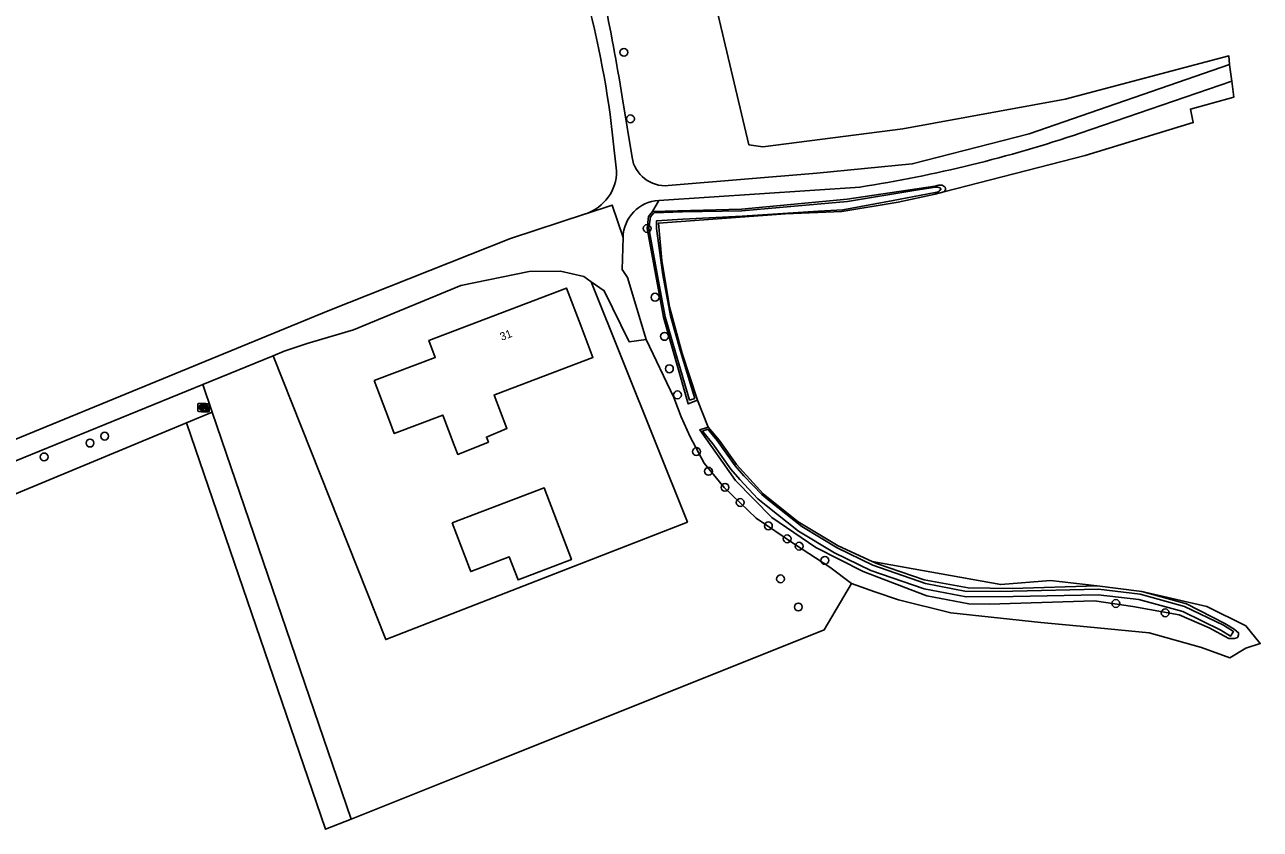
# Model space of a CAD drawing. Extents: x 162515 to 163909, y 388494 to 389773.
# Drawn here: x 162727.4 to 162881.8, y 389491.8 to 389592.3 of the extents above; entities that cross this region are included whole.
import ezdxf

# ---------------------------------------------------------------- set-up
doc = ezdxf.new("R2010")
doc.units = 0
for name, color, linetype in [('IMGEO_Boom', 7, 'Continuous'), ('IMGEO_Grasland_agrarisch', 7, 'Continuous'), ('IMGEO_Grasland_overig', 7, 'Continuous'), ('IMGEO_Groenvoorziening', 7, 'Continuous'), ('IMGEO_Kast', 7, 'Continuous'), ('IMGEO_Loofbos', 7, 'Continuous'), ('IMGEO_Pand', 7, 'Continuous'), ('IMGEO_Pand_nummerreeks', 7, 'Continuous'), ('IMGEO_Rijbaan_lokaal_onverhard', 7, 'Continuous'), ('IMGEO_Rioolput', 7, 'Continuous'), ('IMGEO_Waterloop', 7, 'Continuous')]:
    doc.layers.add(name, color=color, linetype=linetype)

msp = doc.modelspace()

# ---------------------------------------------------------------- linework, layer by layer
at = {"layer": 'IMGEO_Boom'}
for centre in [(162802.3, 389588.83), (162803.12, 389580.53), (162805.21, 389566.84), (162806.2, 389558.25), (162807.38, 389553.36), (162807.99, 389549.32), (162809, 389546.06), (162735.58, 389540.04), (162737.42, 389540.9), (162729.85, 389538.31), (162811.37, 389538.98), (162812.88, 389536.52), (162814.93, 389534.51), (162816.84, 389532.62), (162820.36, 389529.7), (162822.7, 389528.09), (162824.2, 389527.16), (162827.42, 389525.39), (162821.88, 389523.08), (162863.78, 389520.01), (162824.1, 389519.57), (162869.95, 389518.84)]:
    msp.add_circle(centre, 0.489, dxfattribs=at)
at = {"layer": 'IMGEO_Grasland_agrarisch'}
for points in [[(162842.3, 389571.4), (162841.22, 389571.12), (162836.57, 389570.12), (162829.53, 389568.94), (162822.51, 389568.67), (162806.61, 389567.52), (162807.04, 389562.82), (162808.01, 389557.04), (162809.58, 389551.22), (162811.51, 389545.39)], [(162758.46, 389550.93), (162772.54, 389515.5), (162810.25, 389530.17), (162798.23, 389560.18)], [(162805.1, 389552.99), (162808.53, 389545.75), (162809.47, 389543.32), (162810.6, 389540.81), (162812.35, 389537.53), (162814.84, 389534.48), (162818.85, 389530.65), (162823.62, 389527.41), (162828.02, 389524.54), (162830.73, 389522.5)], [(162811.51, 389545.39), (162812.84, 389542.03)], [(162812.84, 389542.03), (162814.21, 389540.4), (162816.36, 389537.36), (162819.72, 389533.71), (162824.1, 389530.21), (162829.09, 389527.19), (162833.31, 389525.27)], [(162830.73, 389522.5), (162827.33, 389516.71), (162785.51, 389500), (162768.2, 389493.08)], [(162867.02, 389521.52), (162875.15, 389519.62), (162880.03, 389517.23), (162881.83, 389515.01), (162880.03, 389514.44), (162878.02, 389513.24), (162874.5, 389514.52), (162867.96, 389516.36), (162860.18, 389517.1), (162854.42, 389517.64), (162843.15, 389518.83), (162836.62, 389520.46), (162833.65, 389521.45), (162830.73, 389522.5)], [(162861.43, 389522.21), (162867.02, 389521.52)]]:
    msp.add_lwpolyline(points, dxfattribs=at)
at = {"layer": 'IMGEO_Grasland_overig'}
for points in [[(162821.12, 389656.85), (162822.63, 389656.45), (162822.63, 389655.29), (162821.47, 389651.89), (162809.57, 389646.73), (162801.62, 389643.91), (162810.38, 389609.16), (162817.93, 389577.28), (162819.66, 389577.03), (162837.14, 389579.3), (162857.44, 389582.98), (162877.92, 389588.38), (162877.98, 389587.31)], [(162807.85, 389572.19), (162826.4, 389573.73), (162838.34, 389574.9), (162852.96, 389578.66), (162877.98, 389587.31)], [(162877.98, 389587.31), (162877.98, 389587.29), (162878.28, 389585.23)], [(162878.28, 389585.23), (162878.52, 389583.25), (162873.09, 389581.75), (162873.45, 389580.07), (162859.94, 389575.96), (162842.3, 389571.4)], [(162878.28, 389585.23), (162859.33, 389578.75)], [(162802.08, 389583.27), (162803.32, 389575.72)], [(162801.39, 389574.04), (162800.58, 389581.05)], [(162841.32, 389572.18), (162841.18, 389572.14), (162830.22, 389570.48), (162817, 389569.23), (162805.88, 389568.97)], [(162831.81, 389572), (162806.66, 389570.35)], [(162805.88, 389568.97), (162806.66, 389570.35)], [(162750.86, 389543.91), (162768.2, 389493.08)], [(162768.2, 389493.08), (162765.02, 389491.82), (162747.64, 389542.57)], [(162861.43, 389522.21), (162850.81, 389521.9), (162845.33, 389521.98), (162839.84, 389522.97), (162834.01, 389524.95), (162833.31, 389525.27)], [(162833.31, 389525.27), (162849.39, 389522.37), (162855.61, 389522.9), (162861.43, 389522.21)]]:
    msp.add_lwpolyline(points, dxfattribs=at)
for centre, radius, start, end in [((162566.49, 389545.95), 238.53, 9.002, 15.1352), ((162675.11, 389563.51), 126.69, 7.9603, 16.7021), ((162806.23, 389735.88), 165.86, 278.8707, 288.6722), ((162807.49, 389576.4), 4.23, 189.3024, 274.8899), ((162795.74, 389574.03), 5.65, 288.5666, 0.0028), ((162841.82, 389570.59), 1.66, 86.1747, 107.4738), ((162841.9, 389571.58), 0.671, 37.4613, 87.2296), ((162842.05, 389571.77), 0.445, 304.435, 30.1996), ((162806.96, 389565.59), 4.77, 93.6538, 178.328)]:
    msp.add_arc(centre, radius, start, end, dxfattribs=at)
at = {"layer": 'IMGEO_Groenvoorziening'}
for points in [[(162811.51, 389545.39), (162810.34, 389544.94), (162807.27, 389555.78), (162805.21, 389566.84), (162805.39, 389568.34), (162805.88, 389568.97)], [(162867.02, 389521.52), (162872.63, 389519.97), (162877.42, 389517.51), (162878.58, 389516.79), (162879.11, 389516.35), (162879.11, 389516.11), (162879.02, 389515.82), (162878.89, 389515.72), (162878.59, 389515.65), (162877.88, 389515.64), (162875.46, 389516.96), (162871.68, 389518.6), (162865.89, 389519.65), (162861.1, 389520.33), (162847.93, 389519.91), (162845.39, 389519.97), (162840.14, 389520.96), (162838.96, 389521.41), (162832.2, 389524), (162826.27, 389527), (162820.8, 389530.76), (162816.24, 389535.38), (162811.78, 389541.68), (162812.84, 389542.03)]]:
    msp.add_lwpolyline(points, dxfattribs=at)
at = {"layer": 'IMGEO_Kast'}
for p, q in [((162749.48, 389544.02), (162749.48, 389544.86)), ((162749.48, 389544.86), (162749.48, 389544.02)), ((162749.56, 389544.94), (162750.4, 389544.94)), ((162750.4, 389544.94), (162749.56, 389544.94)), ((162750.48, 389544.87), (162750.48, 389544.03)), ((162750.48, 389544.03), (162750.48, 389544.87)), ((162750.41, 389543.94), (162749.57, 389543.94)), ((162749.57, 389543.94), (162750.41, 389543.94))]:
    msp.add_line(p, q, dxfattribs=at)
for points in [[(162749.68, 389544.73), (162750.28, 389544.73), (162750.28, 389544.65), (162749.68, 389544.65), (162749.68, 389544.73)], [(162749.68, 389544.56), (162750.28, 389544.56), (162750.28, 389544.07), (162749.68, 389544.07), (162749.68, 389544.56)]]:
    msp.add_lwpolyline(points, dxfattribs=at)
msp.add_circle((162749.76, 389544.41), 0.0377, dxfattribs=at)
for centre, start, end in [((162749.56, 389544.86), 92.4484, 184.2845), ((162749.56, 389544.86), 92.4484, 184.2845), ((162750.41, 389544.86), 2.4484, 94.2845), ((162750.41, 389544.86), 2.4484, 94.2845), ((162749.56, 389544.02), 182.4484, 274.2845), ((162749.56, 389544.02), 182.4484, 274.2845), ((162750.41, 389544.02), 272.4484, 4.2845), ((162750.41, 389544.02), 272.4484, 4.2845)]:
    msp.add_arc(centre, 0.0779, start, end, dxfattribs=at)
at = {"layer": 'IMGEO_Loofbos'}
for points in [[(162749.68, 389547.35), (162750.86, 389543.91)], [(162750.86, 389543.91), (162747.64, 389542.57)], [(162747.64, 389542.57), (162673.74, 389511.91)]]:
    msp.add_lwpolyline(points, dxfattribs=at)
at = {"layer": 'IMGEO_Pand'}
for points in [[(162771.09, 389547.84), (162778.73, 389550.74), (162777.93, 389552.85), (162795.14, 389559.39), (162796.92, 389554.71), (162798.43, 389550.73), (162786.27, 389546.11), (162786.07, 389546.03), (162787.69, 389541.87), (162785.12, 389540.78), (162785.38, 389540.17), (162781.54, 389538.63), (162781.11, 389539.76), (162779.67, 389543.54), (162773.6, 389541.23), (162772.87, 389543.16), (162771.09, 389547.84)], [(162780.85, 389530.07), (162792.35, 389534.44), (162795.74, 389525.49), (162789.07, 389522.96), (162787.98, 389525.83), (162783.16, 389524), (162782.99, 389524.43), (162780.85, 389530.07)]]:
    msp.add_lwpolyline(points, dxfattribs=at)
at = {"layer": 'IMGEO_Rijbaan_lokaal_onverhard'}
for points in [[(162797.54, 389568.68), (162800.82, 389569.76), (162802.2, 389565.73)], [(162675.54, 389519.85), (162679.52, 389521.34), (162765.33, 389556.56), (162788.12, 389565.57), (162797.51, 389568.67), (162797.54, 389568.68)], [(162802.2, 389565.73), (162802.08, 389561.71), (162802.74, 389560.7), (162805.1, 389552.99)], [(162798.23, 389560.18), (162797.3, 389560.83), (162794.38, 389561.5), (162790.45, 389561.45), (162781.93, 389559.73), (162768.52, 389554.18), (162762.7, 389552.48), (162759.86, 389551.5), (162758.46, 389550.93)], [(162798.23, 389560.18), (162799.84, 389559.06), (162802.98, 389552.67), (162805.1, 389552.99)], [(162749.68, 389547.35), (162758.46, 389550.93)], [(162678.22, 389518.21), (162749.68, 389547.35)]]:
    msp.add_lwpolyline(points, dxfattribs=at)
at = {"layer": 'IMGEO_Rioolput'}
for p, q in [((162749.07, 389544.07), (162749.07, 389544.93)), ((162749.14, 389545), (162749.99, 389545)), ((162750.07, 389544.93), (162750.07, 389544.07)), ((162749.99, 389544), (162749.14, 389544)), ((162749.55, 389544.78), (162749.58, 389544.78)), ((162749.58, 389544.22), (162749.55, 389544.22))]:
    msp.add_line(p, q, dxfattribs=at)
for points in [[(162749.07, 389544.07), (162749.07, 389544.93)], [(162749.14, 389545), (162749.99, 389545)], [(162750.07, 389544.93), (162750.07, 389544.07)], [(162749.99, 389544), (162749.14, 389544)], [(162749.66, 389544.7), (162749.4, 389544.7), (162749.4, 389544.3)], [(162749.4, 389544.3), (162749.53, 389544.3), (162749.53, 389544.46), (162749.54, 389544.46)], [(162749.58, 389544.62), (162749.53, 389544.62), (162749.53, 389544.54)], [(162749.53, 389544.54), (162749.58, 389544.54)], [(162749.58, 389544.43), (162749.66, 389544.3), (162749.8, 389544.3), (162749.73, 389544.43)]]:
    msp.add_lwpolyline(points, dxfattribs=at)
for centre, radius, start, end in [((162749.14, 389544.92), 0.0765, 91.552, 178.448), ((162749.14, 389544.92), 0.0765, 91.552, 178.448), ((162749.99, 389544.92), 0.0765, 1.552, 88.448), ((162749.99, 389544.92), 0.0765, 1.552, 88.448), ((162749.14, 389544.07), 0.0765, 181.552, 268.448), ((162749.14, 389544.07), 0.0765, 181.552, 268.448), ((162749.54, 389544.41), 0.0533, 26.0293, 88.6989), ((162749.59, 389544.52), 0.0964, 77.0061, 93.1865), ((162749.56, 389544.73), 0.19, 274.7715, 282.9687), ((162749.6, 389544.58), 0.0378, 276.6634, 79.6772), ((162749.65, 389544.59), 0.109, 350.3612, 89.416), ((162749.65, 389544.59), 0.112, 277.5842, 350.9817), ((162749.64, 389544.37), 0.108, 29.5134, 73.7905), ((162749.99, 389544.07), 0.0765, 271.552, 358.448), ((162749.99, 389544.07), 0.0765, 271.552, 358.448)]:
    msp.add_arc(centre, radius, start, end, dxfattribs=at)
for centre, major_axis, ratio, start_param, end_param in [((162749.55, 389544.5), (-0.387, 0.002), 0.722429, 4.712389, 7.853982), ((162749.58, 389544.5), (-0.39, 0.002), 0.717154, 1.570796, 4.712389)]:
    msp.add_ellipse(centre, major_axis=major_axis, ratio=ratio, start_param=start_param, end_param=end_param, dxfattribs=at)
at = {"layer": 'IMGEO_Waterloop'}
for points in [[(162841.43, 389571.35), (162841.21, 389571.31), (162835.97, 389570.33), (162829.68, 389569.17), (162826.61, 389569), (162817.1, 389568.39), (162809.68, 389568), (162806.39, 389567.81), (162806.38, 389566.85), (162807.15, 389561.06), (162808.13, 389555.95), (162809.38, 389551.53), (162811.16, 389545.61), (162810.51, 389545.41), (162808.73, 389551.34), (162807.48, 389555.8), (162806.49, 389560.94), (162805.4, 389566.89), (162805.63, 389568.3), (162806.05, 389568.79), (162809.61, 389568.9), (162817.06, 389569.06), (162826.47, 389569.86), (162830.25, 389570.2), (162838.8, 389571.61), (162841.24, 389571.99)], [(162841.81, 389571.9), (162841.86, 389571.85), (162841.9, 389571.79), (162841.91, 389571.74), (162841.89, 389571.69)], [(162812.81, 389541.77), (162812.11, 389541.54), (162813.4, 389539.94), (162815.66, 389536.77), (162816.78, 389535.5), (162819.05, 389533.09), (162820.1, 389532.24), (162824.14, 389529.04), (162828.63, 389526.33), (162833.15, 389524.14), (162839.83, 389521.83), (162845.07, 389520.83), (162850.93, 389520.87), (162861.58, 389521.09), (162866.67, 389520.52), (162872.14, 389519), (162876.89, 389516.69), (162878.11, 389515.94), (162878.47, 389516.52), (162877.23, 389517.29), (162872.38, 389519.64), (162866.8, 389521.19), (162861.61, 389521.78), (162850.92, 389521.56), (162845.13, 389521.52), (162840, 389522.5), (162833.41, 389524.78), (162828.96, 389526.94), (162824.53, 389529.61), (162820.53, 389532.78), (162819.52, 389533.6), (162817.28, 389535.96), (162816.2, 389537.19), (162813.94, 389540.35), (162812.81, 389541.77)]]:
    msp.add_lwpolyline(points, dxfattribs=at)
for centre, radius, start, end in [((162841.4, 389571.18), 0.825, 60.0258, 101.0496), ((162841.19, 389572.17), 0.847, 286.2259, 325.4584)]:
    msp.add_arc(centre, radius, start, end, dxfattribs=at)

# ---------------------------------------------------------------- texts
at = {"layer": 'IMGEO_Pand_nummerreeks'}
msp.add_text('31', height=1, rotation=20.7926, dxfattribs=at).set_placement((162787.03, 389552.8))

doc.saveas('drawing.dxf')
